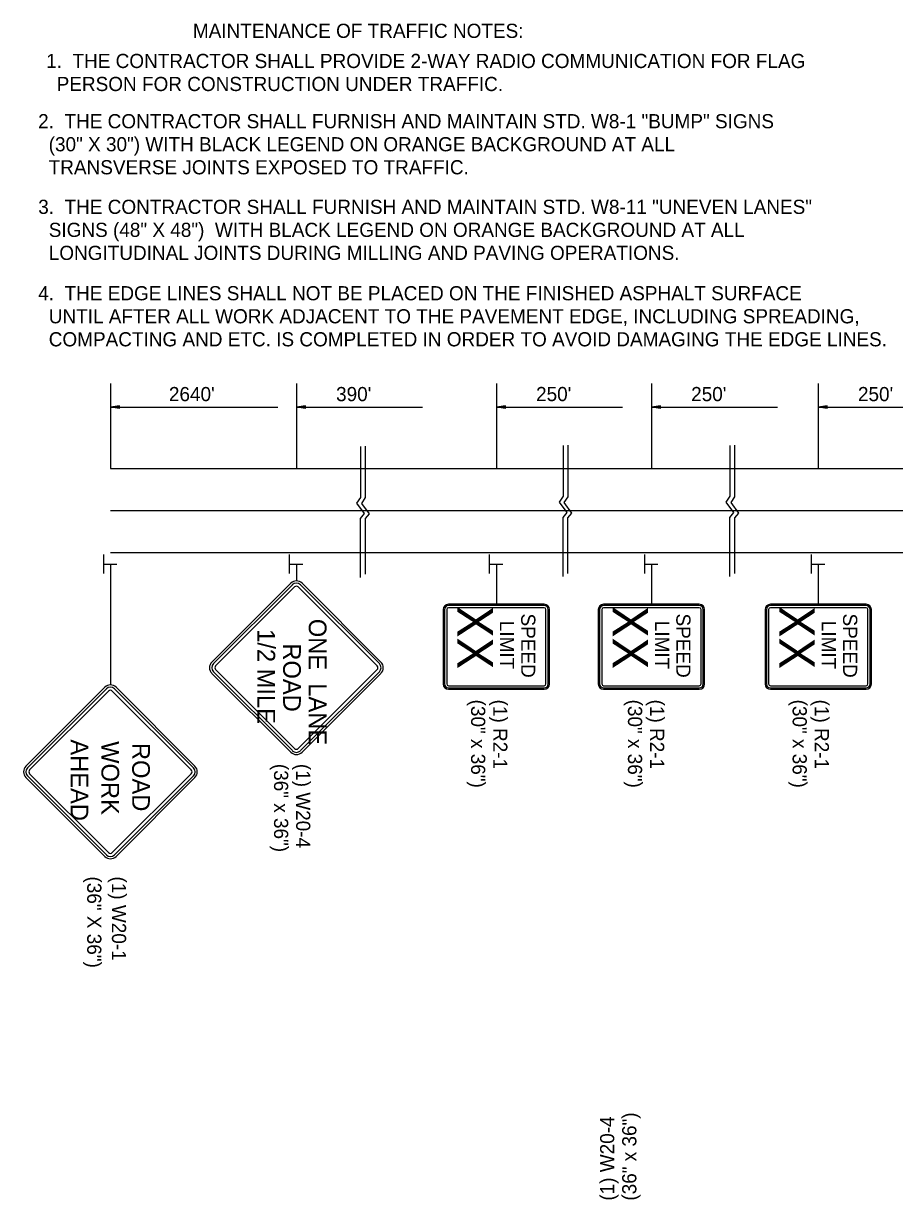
# Model space of a CAD drawing. Extents: x 1927831 to 1930787, y 596452 to 597699.
# Drawn here: x 1927871.5 to 1928240.2, y 597196.1 to 597694.1 of the extents above; entities that cross this region are included whole.
import ezdxf

# ---------------------------------------------------------------- set-up
doc = ezdxf.new("R2010")
doc.units = 0
for name, color, linetype in [('Default', 7, 'Continuous'), ('P_TC_Signs_Permanent', 7, 'Continuous'), ('P_TC_Signs_Temporary', 7, 'Continuous'), ('R_Border', 7, 'Continuous')]:
    doc.layers.add(name, color=color, linetype=linetype)

msp = doc.modelspace()

# ---------------------------------------------------------------- linework, layer by layer
at = {"layer": 'Default'}
for p, q in [((1927908.3, 597541.61), (1927908.3, 597505.58)), ((1927987.03, 597541.61), (1927987.03, 597505.56)), ((1928071.69, 597541.61), (1928071.69, 597505.58)), ((1928137.35, 597541.61), (1928137.35, 597505.58)), ((1928207.95, 597541.61), (1928207.95, 597505.58)), ((1927912.18, 597532.14), (1927908.34, 597531.57)), ((1927912.18, 597530.99), (1927908.34, 597531.57)), ((1927908.34, 597531.57), (1927979.22, 597531.57)), ((1927912.18, 597532.05), (1927908.98, 597531.57)), ((1927912.18, 597531.09), (1927908.98, 597531.57)), ((1927912.18, 597531.95), (1927909.64, 597531.57)), ((1927912.18, 597531.18), (1927909.64, 597531.57)), ((1927912.18, 597531.85), (1927910.28, 597531.57)), ((1927912.18, 597531.28), (1927910.28, 597531.57)), ((1927912.18, 597531.75), (1927910.93, 597531.57)), ((1927912.18, 597531.38), (1927910.93, 597531.57)), ((1927912.18, 597531.66), (1927911.57, 597531.57)), ((1927912.18, 597531.48), (1927911.57, 597531.57)), ((1927912.18, 597530.99), (1927912.18, 597532.14)), ((1927990.87, 597532.14), (1927987.03, 597531.57)), ((1927990.87, 597530.99), (1927987.03, 597531.57)), ((1927987.03, 597531.57), (1928040.44, 597531.57)), ((1927990.87, 597532.05), (1927987.67, 597531.57)), ((1927990.87, 597531.09), (1927987.67, 597531.57)), ((1927990.87, 597531.95), (1927988.33, 597531.57)), ((1927990.87, 597531.18), (1927988.33, 597531.57)), ((1927990.87, 597531.85), (1927988.97, 597531.57)), ((1927990.87, 597531.28), (1927988.97, 597531.57)), ((1927990.87, 597531.75), (1927989.62, 597531.57)), ((1927990.87, 597531.38), (1927989.62, 597531.57)), ((1927990.87, 597531.66), (1927990.26, 597531.57)), ((1927990.87, 597531.48), (1927990.26, 597531.57)), ((1927990.87, 597530.99), (1927990.87, 597532.14)), ((1928075.53, 597532.14), (1928071.69, 597531.57)), ((1928071.69, 597531.57), (1928125.09, 597531.57)), ((1928075.53, 597530.99), (1928071.69, 597531.57)), ((1928075.53, 597532.05), (1928072.33, 597531.57)), ((1928075.53, 597531.09), (1928072.33, 597531.57)), ((1928075.53, 597531.95), (1928072.99, 597531.57)), ((1928075.53, 597531.18), (1928072.99, 597531.57)), ((1928075.53, 597531.85), (1928073.63, 597531.57)), ((1928075.53, 597531.28), (1928073.63, 597531.57)), ((1928075.53, 597531.75), (1928074.28, 597531.57)), ((1928075.53, 597531.38), (1928074.28, 597531.57)), ((1928075.53, 597531.66), (1928074.92, 597531.57)), ((1928075.53, 597531.48), (1928074.92, 597531.57)), ((1928075.53, 597530.99), (1928075.53, 597532.14)), ((1928141.18, 597532.14), (1928137.35, 597531.57)), ((1928137.35, 597531.57), (1928190.75, 597531.57)), ((1928141.18, 597530.99), (1928137.35, 597531.57)), ((1928141.18, 597532.05), (1928137.99, 597531.57)), ((1928141.18, 597531.09), (1928137.99, 597531.57)), ((1928141.18, 597531.95), (1928138.65, 597531.57)), ((1928141.18, 597531.18), (1928138.65, 597531.57)), ((1928141.18, 597531.85), (1928139.29, 597531.57)), ((1928141.18, 597531.28), (1928139.29, 597531.57)), ((1928141.18, 597531.75), (1928139.94, 597531.57)), ((1928141.18, 597531.38), (1928139.94, 597531.57)), ((1928141.18, 597531.66), (1928140.58, 597531.57)), ((1928141.18, 597531.48), (1928140.58, 597531.57)), ((1928141.18, 597530.99), (1928141.18, 597532.14)), ((1928211.79, 597532.14), (1928207.95, 597531.57)), ((1928207.95, 597531.57), (1928261.36, 597531.59)), ((1928211.79, 597530.99), (1928207.95, 597531.57)), ((1928211.79, 597532.05), (1928208.6, 597531.57)), ((1928211.79, 597531.09), (1928208.6, 597531.57)), ((1928211.79, 597531.95), (1928209.26, 597531.57)), ((1928211.79, 597531.18), (1928209.26, 597531.57)), ((1928211.79, 597531.85), (1928209.89, 597531.57)), ((1928211.79, 597531.28), (1928209.89, 597531.57)), ((1928211.79, 597531.75), (1928210.55, 597531.57)), ((1928211.79, 597531.38), (1928210.55, 597531.57)), ((1928211.79, 597531.66), (1928211.19, 597531.57)), ((1928211.79, 597531.48), (1928211.19, 597531.57)), ((1928211.79, 597530.99), (1928211.79, 597532.14)), ((1927908.3, 597505.58), (1928044.85, 597505.58)), ((1928044.85, 597505.58), (1929173.7, 597505.58)), ((1927908.3, 597487.79), (1929173.7, 597487.79)), ((1927905.45, 597461.2), (1927905.45, 597469.2)), ((1927908.3, 597470), (1928044.85, 597470)), ((1927984.18, 597461.2), (1927984.18, 597469.2)), ((1928044.85, 597470), (1929173.7, 597470)), ((1928068.84, 597461.2), (1928068.84, 597469.2)), ((1928134.5, 597461.2), (1928134.5, 597469.2)), ((1928205.1, 597461.2), (1928205.1, 597469.2)), ((1927905.57, 597465.18), (1927911.03, 597465.18)), ((1927984.3, 597465.18), (1927989.77, 597465.18)), ((1928068.96, 597465.18), (1928074.42, 597465.18)), ((1928134.61, 597465.18), (1928140.08, 597465.18)), ((1928205.22, 597465.18), (1928210.69, 597465.18))]:
    msp.add_line(p, q, dxfattribs=at)
for points in [[(1928014.17, 597514.95), (1928014.17, 597493.43), (1928012.5, 597490.96), (1928015.74, 597486.53), (1928014.04, 597484.48), (1928014.03, 597459.46)], [(1928016.21, 597515.15), (1928016.21, 597493.34), (1928014.55, 597490.87), (1928017.79, 597486.44), (1928016.08, 597484.4), (1928016.08, 597460.9)], [(1928099.91, 597515.4), (1928099.91, 597493.87), (1928098.25, 597491.4), (1928101.48, 597486.97), (1928099.78, 597484.93), (1928099.77, 597459.9)], [(1928101.95, 597515.49), (1928101.95, 597493.69), (1928100.29, 597491.21), (1928103.53, 597486.78), (1928101.82, 597484.74), (1928101.82, 597461.24)], [(1928170.52, 597515.4), (1928170.52, 597493.87), (1928168.85, 597491.4), (1928172.09, 597486.97), (1928170.39, 597484.93), (1928170.38, 597459.9)], [(1928172.56, 597515.49), (1928172.56, 597493.69), (1928170.9, 597491.21), (1928174.14, 597486.78), (1928172.43, 597484.74), (1928172.43, 597461.24)]]:
    msp.add_lwpolyline(points, dxfattribs=at)
at = {"layer": 'P_TC_Signs_Permanent'}
for p, q in [((1928049.19, 597445.9), (1928049.19, 597414.4)), ((1928049.75, 597445.9), (1928049.75, 597414.4)), ((1928050.69, 597445.9), (1928050.69, 597414.4)), ((1928091.94, 597448.15), (1928051.44, 597448.15)), ((1928091.94, 597447.59), (1928051.44, 597447.59)), ((1928091.94, 597446.65), (1928051.44, 597446.65)), ((1928092.69, 597414.4), (1928092.69, 597445.9)), ((1928093.63, 597414.4), (1928093.63, 597445.9)), ((1928094.19, 597414.4), (1928094.19, 597445.9)), ((1928114.85, 597445.9), (1928114.85, 597414.4)), ((1928115.41, 597445.9), (1928115.41, 597414.4)), ((1928116.35, 597445.9), (1928116.35, 597414.4)), ((1928157.6, 597448.15), (1928117.1, 597448.15)), ((1928157.6, 597447.59), (1928117.1, 597447.59)), ((1928157.6, 597446.65), (1928117.1, 597446.65)), ((1928158.35, 597414.4), (1928158.35, 597445.9)), ((1928159.28, 597414.4), (1928159.28, 597445.9)), ((1928159.85, 597414.4), (1928159.85, 597445.9)), ((1928185.45, 597445.9), (1928185.45, 597414.4)), ((1928186.02, 597445.9), (1928186.02, 597414.4)), ((1928186.95, 597445.9), (1928186.95, 597414.4)), ((1928228.2, 597448.15), (1928187.7, 597448.15)), ((1928228.2, 597447.59), (1928187.7, 597447.59)), ((1928228.2, 597446.65), (1928187.7, 597446.65)), ((1928228.95, 597414.4), (1928228.95, 597445.9)), ((1928229.89, 597414.4), (1928229.89, 597445.9)), ((1928230.45, 597414.4), (1928230.45, 597445.9)), ((1928051.44, 597413.65), (1928091.94, 597413.65)), ((1928117.1, 597413.65), (1928157.6, 597413.65)), ((1928187.7, 597413.65), (1928228.2, 597413.65)), ((1928051.44, 597412.71), (1928091.94, 597412.71)), ((1928051.44, 597412.15), (1928091.94, 597412.15)), ((1928117.1, 597412.71), (1928157.6, 597412.71)), ((1928117.1, 597412.15), (1928157.6, 597412.15)), ((1928187.7, 597412.71), (1928228.2, 597412.71)), ((1928187.7, 597412.15), (1928228.2, 597412.15))]:
    msp.add_line(p, q, dxfattribs=at)
for centre, radius, start, end in [((1928051.44, 597445.9), 2.25, 90, 180), ((1928051.44, 597445.9), 1.69, 90, 180), ((1928051.44, 597445.9), 0.75, 90, 180), ((1928091.94, 597445.9), 2.25, 360, 90), ((1928091.94, 597445.9), 1.69, 360, 90), ((1928091.94, 597445.9), 0.75, 360, 90), ((1928117.1, 597445.9), 2.25, 90, 180), ((1928117.1, 597445.9), 1.69, 90, 180), ((1928117.1, 597445.9), 0.75, 90, 180), ((1928157.6, 597445.9), 2.25, 360, 90), ((1928157.6, 597445.9), 1.69, 360, 90), ((1928157.6, 597445.9), 0.75, 360, 90), ((1928187.7, 597445.9), 2.25, 90, 180), ((1928187.7, 597445.9), 1.69, 90, 180), ((1928187.7, 597445.9), 0.75, 90, 180), ((1928228.2, 597445.9), 2.25, 360, 90), ((1928228.2, 597445.9), 1.69, 360, 90), ((1928228.2, 597445.9), 0.75, 360, 90), ((1928051.44, 597414.4), 2.25, 180, 270), ((1928051.44, 597414.4), 1.69, 180, 270), ((1928051.44, 597414.4), 0.75, 180, 270), ((1928091.94, 597414.4), 2.25, 270, 360), ((1928091.94, 597414.4), 1.69, 270, 360), ((1928091.94, 597414.4), 0.75, 270, 360), ((1928117.1, 597414.4), 2.25, 180, 270), ((1928117.1, 597414.4), 1.69, 180, 270), ((1928117.1, 597414.4), 0.75, 180, 270), ((1928157.6, 597414.4), 2.25, 270, 360), ((1928157.6, 597414.4), 1.69, 270, 360), ((1928157.6, 597414.4), 0.75, 270, 360), ((1928187.7, 597414.4), 2.25, 180, 270), ((1928187.7, 597414.4), 1.69, 180, 270), ((1928187.7, 597414.4), 0.75, 180, 270), ((1928228.2, 597414.4), 2.25, 270, 360), ((1928228.2, 597414.4), 1.69, 270, 360), ((1928228.2, 597414.4), 0.75, 270, 360)]:
    msp.add_arc(centre, radius, start, end, dxfattribs=at)
at = {"layer": 'P_TC_Signs_Temporary'}
for p, q in [((1927951.24, 597423.67), (1927984.65, 597457.08)), ((1927951.9, 597423), (1927985.31, 597456.42)), ((1927952.83, 597422.08), (1927986.24, 597455.49)), ((1927987.83, 597455.49), (1928021.24, 597422.08)), ((1927988.76, 597456.42), (1928022.17, 597423)), ((1927989.42, 597457.08), (1928022.83, 597423.67)), ((1927984.65, 597385.48), (1927951.24, 597418.89)), ((1927985.31, 597386.15), (1927951.9, 597419.56)), ((1927986.24, 597387.07), (1927952.83, 597420.49)), ((1928021.24, 597420.49), (1927987.83, 597387.07)), ((1928022.17, 597419.56), (1927988.76, 597386.15)), ((1928022.83, 597418.89), (1927989.42, 597385.48)), ((1927872.5, 597379.57), (1927905.91, 597412.98)), ((1927873.17, 597378.91), (1927906.58, 597412.32)), ((1927874.09, 597377.98), (1927907.5, 597411.39)), ((1927909.1, 597411.39), (1927942.51, 597377.98)), ((1927910.02, 597412.32), (1927943.43, 597378.91)), ((1927910.69, 597412.98), (1927944.1, 597379.57)), ((1927905.91, 597341.39), (1927872.5, 597374.8)), ((1927906.58, 597342.05), (1927873.17, 597375.46)), ((1927907.5, 597342.98), (1927874.09, 597376.39)), ((1927942.51, 597376.39), (1927909.1, 597342.98)), ((1927943.43, 597375.46), (1927910.02, 597342.05)), ((1927944.1, 597374.8), (1927910.69, 597341.39))]:
    msp.add_line(p, q, dxfattribs=at)
for centre, radius, start, end in [((1927987.03, 597454.69), 3.37, 45, 135), ((1927987.03, 597454.69), 2.44, 45, 135), ((1927987.03, 597454.69), 1.12, 45, 135), ((1927953.62, 597421.28), 3.37, 135, 225), ((1928020.44, 597421.28), 3.37, 315, 45), ((1927953.62, 597421.28), 2.44, 135, 225), ((1927953.62, 597421.28), 1.13, 135, 225), ((1928020.44, 597421.28), 1.13, 315, 45), ((1928020.44, 597421.28), 2.44, 315, 45), ((1927908.3, 597410.59), 3.37, 45, 135), ((1927908.3, 597410.59), 2.44, 45, 135), ((1927908.3, 597410.59), 1.12, 45, 135), ((1927987.03, 597387.87), 3.37, 225, 315), ((1927987.03, 597387.87), 2.44, 225, 315), ((1927987.03, 597387.87), 1.12, 225, 315), ((1927874.89, 597377.18), 3.37, 135, 225), ((1927874.89, 597377.18), 2.44, 135, 225), ((1927941.71, 597377.18), 2.44, 315, 45), ((1927941.71, 597377.18), 3.37, 315, 45), ((1927874.89, 597377.18), 1.13, 135, 225), ((1927941.71, 597377.18), 1.13, 315, 45), ((1927908.3, 597343.77), 3.38, 225, 315), ((1927908.3, 597343.77), 2.44, 225, 315), ((1927908.3, 597343.77), 1.12, 225, 315)]:
    msp.add_arc(centre, radius, start, end, dxfattribs=at)
at = {"layer": 'R_Border'}
for p, q in [((1927908.3, 597465.18), (1927908.3, 597413.97)), ((1927987.03, 597465.18), (1927987.03, 597458.07)), ((1928071.69, 597465.18), (1928071.69, 597448.15)), ((1928137.35, 597465.18), (1928137.35, 597448.15)), ((1928207.95, 597465.18), (1928207.95, 597448.15))]:
    msp.add_line(p, q, dxfattribs=at)

# ---------------------------------------------------------------- texts
at = {"layer": 'Default'}
for s, p in [("2640'", (1927933.06, 597534.16)), ("390'", (1928003.83, 597534.16)), ("250'", (1928088.49, 597534.18)), ("250'", (1928154.15, 597534.16)), ("250'", (1928224.76, 597534.16))]:
    msp.add_text(s, height=6, rotation=360, dxfattribs=at).set_placement(p)
at = {"layer": 'P_TC_Signs_Permanent'}
for s, height, p in [('XX', 15, (1928055.19, 597447.45)), ('SPEED', 6, (1928082.19, 597444.22)), ('XX', 15, (1928120.85, 597447.45)), ('SPEED', 6, (1928147.85, 597444.22)), ('XX', 15, (1928191.45, 597447.45)), ('SPEED', 6, (1928218.45, 597444.22)), ('LIMIT', 6, (1928073.19, 597441.13)), ('LIMIT', 6, (1928138.85, 597441.13)), ('LIMIT', 6, (1928209.45, 597441.13))]:
    msp.add_text(s, height=height, rotation=270, dxfattribs=at).set_placement(p)
at = {"layer": 'P_TC_Signs_Temporary'}
for s, p in [('ONE  LANE', (1927992.28, 597441.98)), ('1/2 MILE', (1927970.53, 597437.6)), ('ROAD', (1927981.41, 597431.59)), (' AHEAD ', (1927891.47, 597393.72)), ('WORK', (1927904.49, 597390.17)), (' ROAD ', (1927917.51, 597392.2))]:
    msp.add_text(s, height=7.5, rotation=270, dxfattribs=at).set_placement(p)
at = {"layer": 'R_Border'}
for s, height, rotation, p in [('MAINTENANCE OF TRAFFIC NOTES:', 6, 360, (1927943.21, 597688)), ('1.  THE CONTRACTOR SHALL PROVIDE 2-WAY RADIO COMMUNICATION FOR FLAG ', 6, 360, (1927881.08, 597675.24)), ('  PERSON FOR CONSTRUCTION UNDER TRAFFIC.', 6, 360, (1927881.08, 597665.49)), ('2.  THE CONTRACTOR SHALL FURNISH AND MAINTAIN STD. W8-1 "BUMP" SIGNS', 6, 360, (1927877.7, 597649.72)), ('  (30" X 30") WITH BLACK LEGEND ON ORANGE BACKGROUND AT ALL ', 6, 360, (1927877.7, 597639.97)), ('  TRANSVERSE JOINTS EXPOSED TO TRAFFIC.', 6, 360, (1927877.7, 597630.22)), ('3.  THE CONTRACTOR SHALL FURNISH AND MAINTAIN STD. W8-11 "UNEVEN LANES" ', 6, 360, (1927877.73, 597613.46)), ('  SIGNS (48" X 48")  WITH BLACK LEGEND ON ORANGE BACKGROUND AT ALL ', 6, 360, (1927877.73, 597603.71)), ('  LONGITUDINAL JOINTS DURING MILLING AND PAVING OPERATIONS.', 6, 360, (1927877.73, 597593.96)), ('4.  THE EDGE LINES SHALL NOT BE PLACED ON THE FINISHED ASPHALT SURFACE', 6, 360, (1927877.73, 597576.87)), ('  UNTIL AFTER ALL WORK ADJACENT TO THE PAVEMENT EDGE, INCLUDING SPREADING,', 6, 360, (1927877.73, 597567.12)), ('  COMPACTING AND ETC. IS COMPLETED IN ORDER TO AVOID DAMAGING THE EDGE LINES.', 6, 360, (1927877.73, 597557.37)), ('(30" x 36")', 5.9996, 270, (1928060.98, 597407.77)), ('(1) R2-1', 6, 270, (1928070.34, 597407.77)), ('(30" x 36")', 5.9996, 270, (1928127.39, 597407.77)), ('(1) R2-1', 6, 270, (1928136.75, 597407.77)), ('(30" x 36")', 5.9996, 270, (1928197.1, 597407.77)), ('(1) R2-1', 6, 270, (1928206.47, 597407.77)), ('(36" x 36")', 5.9996, 270, (1927977.56, 597380.55)), ('(1) W20-4', 6, 270, (1927986.92, 597380.55)), ('(36" X 36")', 6, 270, (1927898.46, 597332.87)), ('(1) W20-1', 6, 270, (1927908.94, 597332.87)), ('(1) W20-4', 6, 90, (1928121.59, 597195.58)), ('(36" x 36")', 5.9996, 90, (1928130.95, 597195.58))]:
    msp.add_text(s, height=height, rotation=rotation, dxfattribs=at).set_placement(p)

doc.saveas('drawing.dxf')
